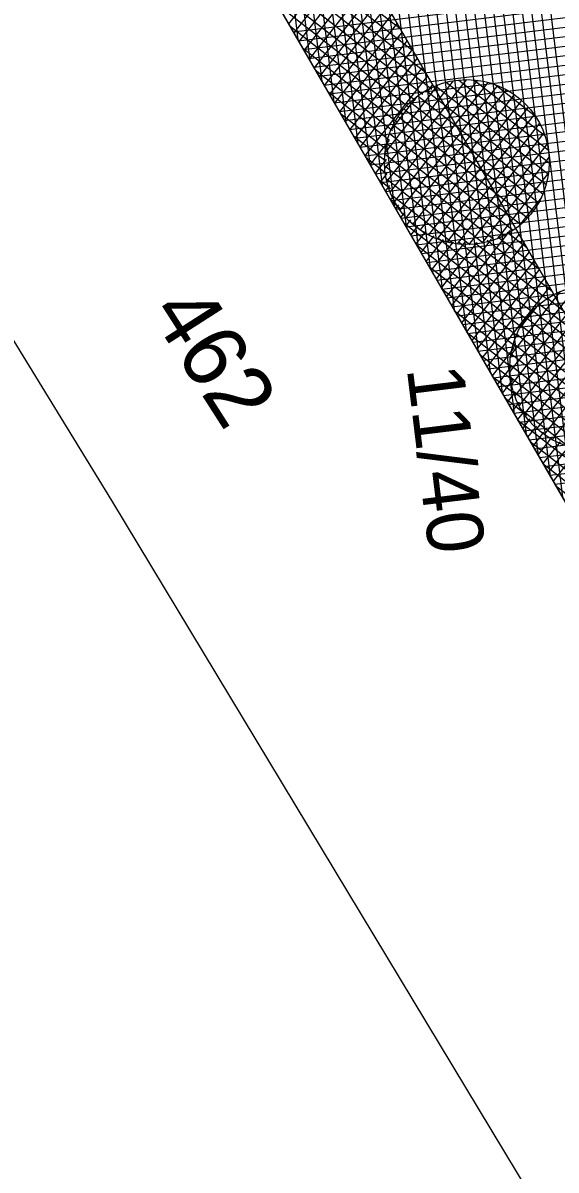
# Model space of a CAD drawing. Extents: x -566982 to -566809, y -1095912 to -1095685.
# Drawn here: x -566930.59 to -566919.27, y -1095795.39 to -1095771.05 of the extents above; entities that cross this region are included whole.
import ezdxf

# ---------------------------------------------------------------- set-up
doc = ezdxf.new("R2010")
doc.units = 0
for name, color, linetype in [('Vrstva 1', 7, 'Continuous'), ('Vrstva 18', 7, 'Continuous'), ('Vrstva 40', 7, 'Continuous'), ('Vrstva 41', 7, 'Continuous'), ('Vrstva 42', 7, 'Continuous'), ('Vrstva 43', 7, 'Continuous'), ('Vrstva 44', 7, 'Continuous')]:
    doc.layers.add(name, color=color, linetype=linetype)

msp = doc.modelspace()

# ---------------------------------------------------------------- linework, layer by layer
at = {"layer": 'Vrstva 1'}
for p, q in [((-566956.66, -1095716.28), (-566892.27, -1095827.53)), ((-566954.26, -1095739.57), (-566928.71, -1095781.18)), ((-566928.71, -1095781.18), (-566901.69, -1095825.95))]:
    msp.add_line(p, q, dxfattribs=at)
at = {"layer": 'Vrstva 41'}
for p, q in [((-566925.729, -1095769.721), (-566922.097, -1095772.563)), ((-566925.461, -1095770.185), (-566922.263, -1095772.687)), ((-566923.543, -1095770.249), (-566924.624, -1095771.631)), ((-566923.187, -1095770.12), (-566924.516, -1095771.817)), ((-566923.079, -1095770.306), (-566924.408, -1095772.004)), ((-566923.684, -1095770.305), (-566922.58, -1095771.169)), ((-566924.41, -1095770.384), (-566924.948, -1095771.071)), ((-566924.157, -1095770.385), (-566924.84, -1095771.258)), ((-566923.882, -1095770.358), (-566924.732, -1095771.444)), ((-566924.596, -1095770.354), (-566921.909, -1095772.456)), ((-566922.971, -1095770.493), (-566924.3, -1095772.19)), ((-566924.229, -1095770.386), (-566922.043, -1095772.097)), ((-566923.93, -1095770.367), (-566922.311, -1095771.633)), ((-566925.192, -1095770.649), (-566922.411, -1095772.825)), ((-566922.863, -1095770.679), (-566924.192, -1095772.377)), ((-566922.755, -1095770.866), (-566924.084, -1095772.563)), ((-566924.923, -1095771.113), (-566922.54, -1095772.978)), ((-566922.647, -1095771.052), (-566923.976, -1095772.75)), ((-566922.539, -1095771.239), (-566923.868, -1095772.937)), ((-566922.432, -1095771.425), (-566923.76, -1095773.123)), ((-566924.655, -1095771.577), (-566922.65, -1095773.146)), ((-566922.324, -1095771.612), (-566923.652, -1095773.31)), ((-566922.216, -1095771.799), (-566923.544, -1095773.496)), ((-566922.108, -1095771.985), (-566923.436, -1095773.683)), ((-566924.386, -1095772.041), (-566922.742, -1095773.328)), ((-566922, -1095772.172), (-566923.328, -1095773.869)), ((-566924.117, -1095772.506), (-566922.811, -1095773.527)), ((-566921.892, -1095772.358), (-566922.01, -1095772.51)), ((-566923.849, -1095772.97), (-566922.858, -1095773.745)), ((-566923.58, -1095773.434), (-566922.878, -1095773.983)), ((-566922.814, -1095773.537), (-566923.22, -1095774.056)), ((-566923.311, -1095773.898), (-566922.86, -1095774.252)), ((-566922.877, -1095773.941), (-566923.112, -1095774.242)), ((-566923.043, -1095774.362), (-566922.785, -1095774.564)), ((-566922.861, -1095774.246), (-566923.004, -1095774.429)), ((-566922.804, -1095774.498), (-566922.896, -1095774.616)), ((-566922.723, -1095774.718), (-566922.788, -1095774.802)), ((-566922.774, -1095774.826), (-566922.563, -1095774.992)), ((-566922.618, -1095774.909), (-566922.68, -1095774.989)), ((-566922.497, -1095775.079), (-566922.572, -1095775.175)), ((-566922.505, -1095775.291), (-566919.882, -1095777.343)), ((-566922.36, -1095775.228), (-566922.464, -1095775.362)), ((-566922.209, -1095775.36), (-566922.356, -1095775.548)), ((-566922.043, -1095775.473), (-566922.248, -1095775.735)), ((-566921.863, -1095775.567), (-566922.14, -1095775.921)), ((-566921.667, -1095775.642), (-566922.032, -1095776.108)), ((-566921.788, -1095775.598), (-566919.754, -1095777.19)), ((-566920.648, -1095775.637), (-566921.6, -1095776.854)), ((-566920.25, -1095775.453), (-566921.492, -1095777.041)), ((-566920.056, -1095775.53), (-566921.385, -1095777.227)), ((-566920.733, -1095775.661), (-566919.356, -1095776.739)), ((-566920.506, -1095775.585), (-566919.625, -1095776.275)), ((-566920.307, -1095775.487), (-566919.893, -1095775.811)), ((-566922.237, -1095775.755), (-566919.993, -1095777.511)), ((-566921.453, -1095775.692), (-566921.924, -1095776.295)), ((-566921.212, -1095775.709), (-566921.816, -1095776.481)), ((-566920.955, -1095775.705), (-566921.708, -1095776.668)), ((-566921.32, -1095775.71), (-566919.607, -1095777.051)), ((-566919.948, -1095775.716), (-566921.277, -1095777.414)), ((-566919.84, -1095775.903), (-566921.169, -1095777.6)), ((-566921.001, -1095775.706), (-566919.441, -1095776.927)), ((-566919.732, -1095776.089), (-566921.061, -1095777.787)), ((-566921.968, -1095776.219), (-566920.083, -1095777.694)), ((-566919.624, -1095776.276), (-566920.953, -1095777.974)), ((-566919.516, -1095776.462), (-566920.845, -1095778.16)), ((-566921.7, -1095776.683), (-566920.153, -1095777.893)), ((-566919.408, -1095776.649), (-566920.737, -1095778.347)), ((-566919.3, -1095776.835), (-566919.313, -1095776.852)), ((-566921.431, -1095777.147), (-566920.199, -1095778.111)), ((-566921.162, -1095777.611), (-566920.218, -1095778.35)), ((-566920.894, -1095778.076), (-566920.198, -1095778.62)), ((-566920.164, -1095777.94), (-566920.629, -1095778.533)), ((-566920.217, -1095778.332), (-566920.521, -1095778.72)), ((-566920.625, -1095778.54), (-566920.119, -1095778.936)), ((-566920.196, -1095778.63), (-566920.413, -1095778.906)), ((-566920.356, -1095779.004), (-566919.891, -1095779.368)), ((-566920.137, -1095778.879), (-566920.305, -1095779.093)), ((-566920.053, -1095779.096), (-566920.197, -1095779.279)), ((-566919.947, -1095779.285), (-566920.089, -1095779.466)), ((-566920.088, -1095779.468), (-566916.71, -1095782.111)), ((-566919.824, -1095779.452), (-566919.981, -1095779.653)), ((-566919.686, -1095779.601), (-566919.873, -1095779.839)), ((-566919.534, -1095779.73), (-566919.765, -1095780.026)), ((-566919.819, -1095779.932), (-566916.857, -1095782.25)), ((-566919.367, -1095779.841), (-566919.657, -1095780.212)), ((-566919.185, -1095779.934), (-566919.549, -1095780.399)), ((-566918.987, -1095780.005), (-566919.441, -1095780.585)), ((-566918.77, -1095780.053), (-566919.333, -1095780.772)), ((-566919.55, -1095780.396), (-566916.985, -1095782.403)), ((-566919.282, -1095780.861), (-566917.095, -1095782.571))]:
    msp.add_line(p, q, dxfattribs=at)
at = {"layer": 'Vrstva 42'}
msp.add_lwpolyline([(-566834.15, -1095760.69), (-566836.072, -1095760.136), (-566841.286, -1095779.189), (-566855.268, -1095796.126), (-566881.984, -1095814.851), (-566891.818, -1095824.318), (-566954.342, -1095716.292), (-566956.66, -1095716.28), (-566892.27, -1095827.53), (-566880.71, -1095816.4), (-566853.9, -1095797.61), (-566839.47, -1095780.13)], close=True, dxfattribs=at)
at = {"layer": 'Vrstva 43'}
for p, q in [((-566927.841, -1095746.108), (-566924.753, -1095771.407)), ((-566927.585, -1095746.549), (-566924.498, -1095771.848)), ((-566927.33, -1095746.99), (-566924.243, -1095772.289)), ((-566927.075, -1095747.432), (-566923.987, -1095772.73)), ((-566926.819, -1095747.873), (-566923.732, -1095773.171)), ((-566926.564, -1095748.314), (-566923.477, -1095773.612)), ((-566926.309, -1095748.755), (-566923.221, -1095774.054)), ((-566926.053, -1095749.196), (-566922.966, -1095774.495)), ((-566925.798, -1095749.637), (-566922.711, -1095774.936)), ((-566925.543, -1095750.078), (-566922.456, -1095775.377)), ((-566925.287, -1095750.519), (-566922.2, -1095775.818)), ((-566925.032, -1095750.96), (-566921.945, -1095776.259)), ((-566924.777, -1095751.402), (-566921.69, -1095776.7)), ((-566924.521, -1095751.843), (-566921.434, -1095777.141)), ((-566924.266, -1095752.284), (-566921.179, -1095777.582)), ((-566924.011, -1095752.725), (-566920.924, -1095778.024)), ((-566923.756, -1095753.166), (-566920.668, -1095778.465)), ((-566923.5, -1095753.607), (-566920.413, -1095778.906)), ((-566923.245, -1095754.048), (-566920.158, -1095779.347)), ((-566922.99, -1095754.489), (-566919.902, -1095779.788)), ((-566922.734, -1095754.931), (-566919.647, -1095780.229)), ((-566922.479, -1095755.372), (-566919.392, -1095780.67)), ((-566922.224, -1095755.813), (-566919.136, -1095781.111)), ((-566921.968, -1095756.254), (-566918.881, -1095781.553)), ((-566921.713, -1095756.695), (-566918.626, -1095781.994)), ((-566921.458, -1095757.136), (-566918.371, -1095782.435)), ((-566921.202, -1095757.577), (-566918.115, -1095782.876)), ((-566920.947, -1095758.018), (-566917.86, -1095783.317)), ((-566924.851, -1095771.238), (-566914.058, -1095769.921)), ((-566924.742, -1095771.426), (-566913.949, -1095770.109)), ((-566924.633, -1095771.614), (-566913.84, -1095770.297)), ((-566924.525, -1095771.802), (-566913.732, -1095770.485)), ((-566924.416, -1095771.99), (-566913.623, -1095770.673)), ((-566924.307, -1095772.179), (-566913.514, -1095770.861)), ((-566924.198, -1095772.367), (-566913.405, -1095771.05)), ((-566924.089, -1095772.555), (-566913.296, -1095771.238)), ((-566923.98, -1095772.743), (-566913.187, -1095771.426)), ((-566923.871, -1095772.931), (-566913.078, -1095771.614)), ((-566923.762, -1095773.12), (-566912.969, -1095771.802)), ((-566923.653, -1095773.308), (-566912.86, -1095771.991)), ((-566923.544, -1095773.496), (-566912.751, -1095772.179)), ((-566923.435, -1095773.684), (-566912.642, -1095772.367)), ((-566923.326, -1095773.872), (-566912.533, -1095772.555)), ((-566923.217, -1095774.06), (-566912.424, -1095772.743)), ((-566923.109, -1095774.249), (-566912.316, -1095772.932)), ((-566923, -1095774.437), (-566912.207, -1095773.12)), ((-566922.891, -1095774.625), (-566912.098, -1095773.308)), ((-566922.782, -1095774.813), (-566911.989, -1095773.496)), ((-566922.673, -1095775.001), (-566911.88, -1095773.684)), ((-566922.564, -1095775.19), (-566911.771, -1095773.873)), ((-566922.455, -1095775.378), (-566911.662, -1095774.061)), ((-566922.346, -1095775.566), (-566911.553, -1095774.249)), ((-566922.237, -1095775.754), (-566911.444, -1095774.437)), ((-566922.128, -1095775.942), (-566911.335, -1095774.625)), ((-566922.019, -1095776.131), (-566911.226, -1095774.813)), ((-566921.91, -1095776.319), (-566911.117, -1095775.002)), ((-566921.801, -1095776.507), (-566911.008, -1095775.19)), ((-566921.693, -1095776.695), (-566910.9, -1095775.378)), ((-566921.584, -1095776.883), (-566910.791, -1095775.566)), ((-566921.475, -1095777.072), (-566910.682, -1095775.754)), ((-566921.366, -1095777.26), (-566910.573, -1095775.943)), ((-566921.257, -1095777.448), (-566910.464, -1095776.131)), ((-566921.148, -1095777.636), (-566910.355, -1095776.319)), ((-566921.039, -1095777.824), (-566910.246, -1095776.507)), ((-566920.93, -1095778.012), (-566910.137, -1095776.695)), ((-566920.821, -1095778.201), (-566910.028, -1095776.884)), ((-566920.712, -1095778.389), (-566909.919, -1095777.072)), ((-566920.603, -1095778.577), (-566909.81, -1095777.26)), ((-566920.494, -1095778.765), (-566909.701, -1095777.448)), ((-566920.385, -1095778.953), (-566909.592, -1095777.636)), ((-566920.277, -1095779.142), (-566909.484, -1095777.825)), ((-566920.168, -1095779.33), (-566909.375, -1095778.013)), ((-566920.059, -1095779.518), (-566909.266, -1095778.201)), ((-566919.95, -1095779.706), (-566909.157, -1095778.389)), ((-566919.841, -1095779.894), (-566909.048, -1095778.577)), ((-566919.732, -1095780.083), (-566908.939, -1095778.766)), ((-566919.623, -1095780.271), (-566908.83, -1095778.954)), ((-566919.514, -1095780.459), (-566908.721, -1095779.142)), ((-566919.405, -1095780.647), (-566908.612, -1095779.33)), ((-566919.296, -1095780.835), (-566908.503, -1095779.518))]:
    msp.add_line(p, q, dxfattribs=at)
msp.add_lwpolyline([(-566834.15, -1095760.69), (-566843.76, -1095757.92), (-566848.55, -1095775.42), (-566860.75, -1095790.2), (-566887.09, -1095808.66), (-566890.01, -1095811.47), (-566945.07, -1095716.34), (-566956.66, -1095716.28), (-566892.27, -1095827.53), (-566880.71, -1095816.4), (-566853.9, -1095797.61), (-566839.47, -1095780.13)], close=True, dxfattribs=at)
at = {"layer": 'Vrstva 44'}
for p, q in [((-566921.182, -1095772.253), (-566922.866, -1095774.404)), ((-566921.337, -1095772.261), (-566919.432, -1095773.752)), ((-566921.015, -1095772.259), (-566919.506, -1095773.44)), ((-566921.455, -1095772.276), (-566922.906, -1095774.131)), ((-566921.777, -1095772.363), (-566922.899, -1095773.797)), ((-566920.939, -1095772.267), (-566922.792, -1095774.634)), ((-566920.719, -1095772.31), (-566922.698, -1095774.839)), ((-566920.517, -1095772.376), (-566922.585, -1095775.019)), ((-566920.33, -1095772.462), (-566922.456, -1095775.178)), ((-566922.028, -1095772.482), (-566919.48, -1095774.476)), ((-566921.829, -1095772.384), (-566919.433, -1095774.259)), ((-566921.601, -1095772.308), (-566919.415, -1095774.019)), ((-566920.562, -1095772.359), (-566919.71, -1095773.026)), ((-566922.224, -1095772.61), (-566922.765, -1095773.302)), ((-566922.363, -1095772.728), (-566919.64, -1095774.859)), ((-566920.16, -1095772.569), (-566922.312, -1095775.319)), ((-566922.206, -1095772.597), (-566919.55, -1095774.675)), ((-566920.003, -1095772.693), (-566922.154, -1095775.441)), ((-566922.5, -1095772.875), (-566919.747, -1095775.029)), ((-566919.86, -1095772.835), (-566921.982, -1095775.547)), ((-566922.721, -1095773.21), (-566920.019, -1095775.324)), ((-566922.62, -1095773.035), (-566919.873, -1095775.184)), ((-566919.732, -1095772.995), (-566921.795, -1095775.632)), ((-566919.62, -1095773.177), (-566921.592, -1095775.697)), ((-566922.805, -1095773.398), (-566920.184, -1095775.449)), ((-566919.527, -1095773.383), (-566921.37, -1095775.738)), ((-566922.866, -1095773.604), (-566920.368, -1095775.559)), ((-566919.456, -1095773.616), (-566921.124, -1095775.749)), ((-566922.902, -1095773.83), (-566920.577, -1095775.649)), ((-566919.418, -1095773.892), (-566920.849, -1095775.722)), ((-566922.911, -1095774.077), (-566920.818, -1095775.715)), ((-566922.874, -1095774.36), (-566921.1, -1095775.748)), ((-566919.43, -1095774.232), (-566920.522, -1095775.628)), ((-566922.767, -1095774.697), (-566921.454, -1095775.725)), ((-566919.582, -1095774.752), (-566920.05, -1095775.349)), ((-566922.393, -1095775.244), (-566922.076, -1095775.492)), ((-566918.567, -1095776.614), (-566920.216, -1095778.722)), ((-566918.318, -1095776.621), (-566920.148, -1095778.96)), ((-566918.846, -1095776.646), (-566920.252, -1095778.444)), ((-566919.18, -1095776.748), (-566920.235, -1095778.097)), ((-566918.096, -1095776.662), (-566920.056, -1095779.167)), ((-566917.891, -1095776.725), (-566919.947, -1095779.351)), ((-566917.702, -1095776.808), (-566919.82, -1095779.514)), ((-566919.686, -1095777.071), (-566920.038, -1095777.521)), ((-566917.528, -1095776.91), (-566919.678, -1095779.657)), ((-566919.619, -1095777.014), (-566916.928, -1095779.12)), ((-566917.37, -1095777.032), (-566919.522, -1095779.783)), ((-566919.452, -1095776.891), (-566916.851, -1095778.927)), ((-566919.898, -1095777.304), (-566917.144, -1095779.459)), ((-566919.768, -1095777.152), (-566917.027, -1095779.297)), ((-566917.225, -1095777.171), (-566919.353, -1095779.89)), ((-566920.011, -1095777.47), (-566917.279, -1095779.607)), ((-566920.176, -1095777.849), (-566917.604, -1095779.861)), ((-566920.103, -1095777.652), (-566917.432, -1095779.742)), ((-566920.228, -1095778.062), (-566917.801, -1095779.961)), ((-566920.253, -1095778.297), (-566918.022, -1095780.042)), ((-566920.242, -1095778.559), (-566918.279, -1095780.095)), ((-566920.18, -1095778.861), (-566918.586, -1095780.108)), ((-566920.015, -1095779.244), (-566918.998, -1095780.04))]:
    msp.add_line(p, q, dxfattribs=at)
for centre in [(-566921.163, -1095774.001), (-566918.505, -1095778.361)]:
    msp.add_circle(centre, 1.75, dxfattribs=at)

# ---------------------------------------------------------------- texts
at = {"layer": 'Vrstva 18'}
msp.add_text('462', height=1.36, rotation=302.634, dxfattribs=at).set_placement((-566927.917, -1095777.191))
at = {"layer": 'Vrstva 40'}
msp.add_text('11/40', height=1.2, rotation=276.9575, dxfattribs=at).set_placement((-566922.442, -1095778.378))

doc.saveas('drawing.dxf')
